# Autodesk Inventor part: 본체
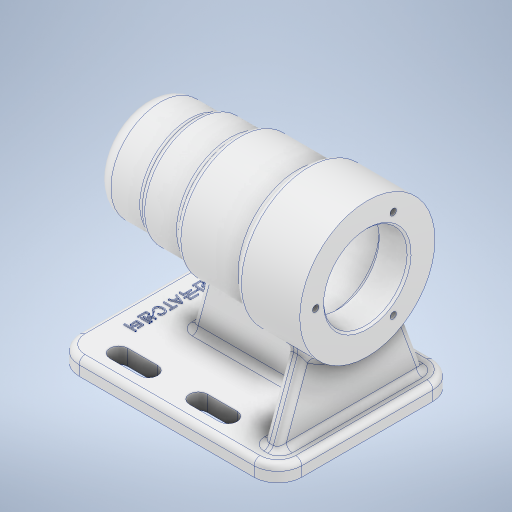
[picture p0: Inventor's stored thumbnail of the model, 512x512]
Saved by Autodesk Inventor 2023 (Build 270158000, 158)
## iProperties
Created: 2022-07
Part Number: 본체
Material: 알루미늄 6061
Document SubType Name: Modeling
Designer: owner
Density: 2.7 g/cm^3
Appearance: 알루미늄 - 평지
Author: owner
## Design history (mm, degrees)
sketch "스케치1"
  geometry: L1 (44, -45)-(-44, -45); L2 (-56, -33)-(-56, 33); L3 (-44, 45)-(44, 45); L4 (56, 33)-(56, -33); L5 (56, -45)-(-56, 45); L6 (-56, -45)-(56, 45); L7 (36, 33)-(21, 33); L8 (36, 37.5)-(21, 37.5); L9 (21, 28.5)-(36, 28.5); L10 (-4, 33)-(-19, 33); L11 (-4, 37.5)-(-19, 37.5); L12 (-19, 28.5)-(-4, 28.5); L13 (56, 0)-(-56, 0); L14 (21, -28.5)-(36, -28.5); L15 (36, -37.5)-(21, -37.5); L16 (-19, -28.5)-(-4, -28.5); L17 (-4, -37.5)-(-19, -37.5); A1 r 12 centre (44, 33) between (56, 33) and (44, 45); A2 r 12 centre (-44, 33) between (-44, 45) and (-56, 33); A3 r 12 centre (-44, -33) between (-56, -33) and (-44, -45); A4 r 12 centre (44, -33) between (44, -45) and (56, -33); A5 r 4.5 centre (36, 33) between (36, 28.5) and (36, 37.5); A6 r 4.5 centre (21, 33) between (21, 37.5) and (21, 28.5); A7 r 4.5 centre (-4, 33) between (-4, 28.5) and (-4, 37.5); A8 r 4.5 centre (-19, 33) between (-19, 37.5) and (-19, 28.5); A9 r 4.5 centre (36, -33) between (36, -37.5) and (36, -28.5); A10 r 4.5 centre (21, -33) between (21, -28.5) and (21, -37.5); A11 r 4.5 centre (-4, -33) between (-4, -37.5) and (-4, -28.5); A12 r 4.5 centre (-19, -33) between (-19, -28.5) and (-19, -37.5); 3 further points
  constraints: 38 end point, 24 point on circle, 16 tangent, 12 centre point, 12 symmetric about line, 8 point on line, 6 midpoint, 4 parallel, 3 equal radius, 3 horizontal, 1 collinear, 1 perpendicular, 4 other
  dimensions: "d0" = 112 distance of L5.end L6.end; "d1" = 90 distance of L6.start L5.end; "d2" = 12 radius of A1; "d3" = 15 distance of L7.start L7.end; "d4" = 9 diameter of A6; "d5" = 33 distance from line of point (0, 0) L7; "d6" = 20 distance from line of L4 L7.start; "d7" = 15 distance of L10.start L10.end; "d8" = 9 diameter of A8; "d9" = 25 distance of L10.start L7.end
extrude "돌출1" new body sketch "스케치1" distance "d10" = 8; taper "d11" = 0 deg
fillet "모깎기1" dims "d12" = 3
sketch "스케치2"
  geometry: L1 (-56, 70)-(56, 70); L2 (56, 0)-(44, 0) reference; L3 (-44, 0)-(44, 0) reference; L4 (-56, 70)-(-56, 87); L5 (-48, 95)-(-33.472, 95); L6 (-32, 95)-(-32, 94); L7 (-29, 97)-(-13, 97); L8 (-10, 100)-(-10, 100); L9 (-7.804, 100)-(21, 100); L10 (24, 103)-(24, 104); L11 (26.657, 104)-(56, 104); L12 (56, 104)-(56, 91); L13 (56, 91)-(41, 91); L14 (41, 91)-(41, 91); L15 (38, 94)-(-10, 94); L16 (-13, 91)-(-13, 91); L17 (-13, 91)-(-24.7, 91); L18 (-25, 90.7)-(-25, 87.5); L19 (-25, 87.5)-(-42.7, 87.5); L20 (-43, 87.2)-(-43, 86); L21 (-43, 86)-(-46.7, 86); L22 (-47, 85.7)-(-47, 80.5); L23 (-47, 80.5)-(-47, 80.5); L24 (-50, 77.5)-(-50, 70); A1 r 0.3 centre (-46.7, 85.7) between (-46.7, 86) and (-47, 85.7); A2 r 0.3 centre (-42.7, 87.2) between (-42.7, 87.5) and (-43, 87.2); A3 r 0.3 centre (-24.7, 90.7) between (-24.7, 91) and (-25, 90.7); A4 r 8 centre (-48, 87) between (-48, 95) and (-56, 87); A5 r 3 centre (-29, 94) between (-29, 97) and (-31.236, 96); A6 r 3 centre (-33.472, 98) between (-33.472, 95) and (-31.236, 96); A7 r 3 centre (-13, 100) between (-13, 97) and (-10.402, 98.5); A8 r 3 centre (-7.804, 97) between (-7.804, 100) and (-10.402, 98.5); A9 r 3 centre (21, 103) between (21, 100) and (23.828, 102); A10 r 3 centre (26.657, 101) between (26.657, 104) and (23.828, 102); A11 r 3 centre (-10, 91) between (-10, 94) and (-13, 91); A12 r 3 centre (38, 91) between (41, 91) and (38, 94); A13 r 3 centre (-47, 77.5) between (-47, 80.5) and (-50, 77.5); 16 further points
  constraints: 44 end point, 29 point on circle, 26 tangent, 24 point on line, 18 perpendicular, 13 centre point, 9 equal radius, 2 horizontal, 2 midpoint, 1 vertical, 1 vertical alignment
  dimensions: "d13" = 112 distance of L1.start L1.end; "d14" = 70 distance between parallel lines of L2 L1; "d15" = 25 distance of L1.start point (-56, 95); "d16" = 24 distance of point (-56, 95) L6.start; "d17" = 2 distance of L6.start point (-32, 97); "d18" = 22 distance of point (-32, 97) point (-10, 97); "d19" = 3 distance of point (-10, 97) L8.end; "d20" = 34 distance of L8.end point (24, 100); "d21" = 4 distance of point (24, 100) L10.end; "d22" = 32 distance of L10.end L11.end; "d23" = 13 distance of L11.end L12.end; "d24" = 15 distance of L12.end L13.end; "d25" = 3 distance of L13.end point (41, 94); "d27" = 54 distance of point (41, 94) point (-13, 94); "d28" = 3 distance of point (-13, 94) L16.end; "d29" = 12 distance of L16.end point (-25, 91); "d30" = 3.5 distance of point (-25, 91) L18.end; "d31" = 18 distance of L18.end point (-43, 87.5); "d32" = 1.5 distance of point (-43, 87.5) L20.end; "d33" = 4 distance of L20.end point (-47, 86); "d34" = 5.5 distance of point (-47, 86) L22.end; "d35" = 3 distance of L22.end point (-50, 80.5); "d36" = 10.5 distance of point (-50, 80.5) L24.end; "d37" = 0.3 radius of A1; "d38" = 8 radius of A4; "d39" = 3 radius of A5; "d40" = 3 radius of A10 (derived)
revolve "회전1" sketch "스케치2" stored, may be unused: angle "d41" = 90 deg
chamfer "모따기1" distance "d42" = 1; stored, may be unused: second distance "d43" = 2, angle "d44" = 45 deg
sketch "스케치3" dims "d52" = 52
  geometry: C1 r 7.5 at (0, 0) reference; 3 further points
  constraints: 2 horizontal alignment, 1 coincident, 2 other
hole "구멍1" sketch "스케치3" at (-26, 0) diameter "d45" = 3.242; stored, may be unused: countersink angle "d49" = 90 deg, drill point angle "d51" = 118 deg; dims "d46" = 8, "d47" = 52, "d48" = 18, "d50" = 11
node "작업 평면1"
sketch "스케치4"
  geometry: L1 (9.591, 45.342)-(-4, 8); L2 (-9, 8)-(0, 8) reference; L3 (-12, 0)-(-12, 5) reference; L4 (33, 0)-(33, 70); L5 (56.409, 45.342)-(70, 8); L6 (0, 8)-(66, 8) reference; L7 (61.5, 8)-(70.5, 8) reference; 1 further point
  constraints: 6 end point, 2 symmetric about line, 1 point on line, 1 vertical, 2 other
  dimensions: "d57" = 110 deg angle of L2 L1; "d58" = 8 distance from line of L3 L1.end
extrude "돌출2" join sketch "스케치4" distance "d59" = 8; taper "d60" = 0 deg
sketch "스케치5"
  geometry: L1 (-29, 43)-(-13, 43) reference; L2 (-19.622, 43)-(-29, 8); L3 (-21, 8)-(-36, 8) reference; L4 (48, 8)-(48, 45.342) reference; 1 further point
  constraints: 2 end point, 2 point on line
  dimensions: "d61" = 77 distance from line of L4 L2.end; "d62" = 105 deg angle of L3 L2
feature "리브1" sketch "스케치5" dims "d63" = 1, "d64" = 8, "d65" = 0, "d66" = 0, "d67" = 1, "d68" = 1
fillet "모깎기2" dims "d69" = 3
fillet "모깎기3" dims "d70" = 3
fillet "모깎기4" dims "d71" = 3
sketch "스케치6"
  geometry: L1 (-56, 33)-(-56, -33) reference; 2 further points
  constraints: 1 horizontal alignment, 1 other
  dimensions: "d72" = 12 distance from line of L1 point (-44, 0)
feature "엠보싱1" sketch "스케치6" dims "d73" = 0.5, "d74" = 0
node "솔리드1"
pattern_circular "원형 패턴1" dims angle "d54" = 360 deg
feature "A9D066F2-1C7D-4E18-AEED-F7BC21143FA4" dims "d45" = 3.242, "d46" = 8, "d47" = 52, "d48" = 18, "d49" = 90 deg, "d50" = 11, "d51" = 118 deg
other parameters: "d56" = -8
